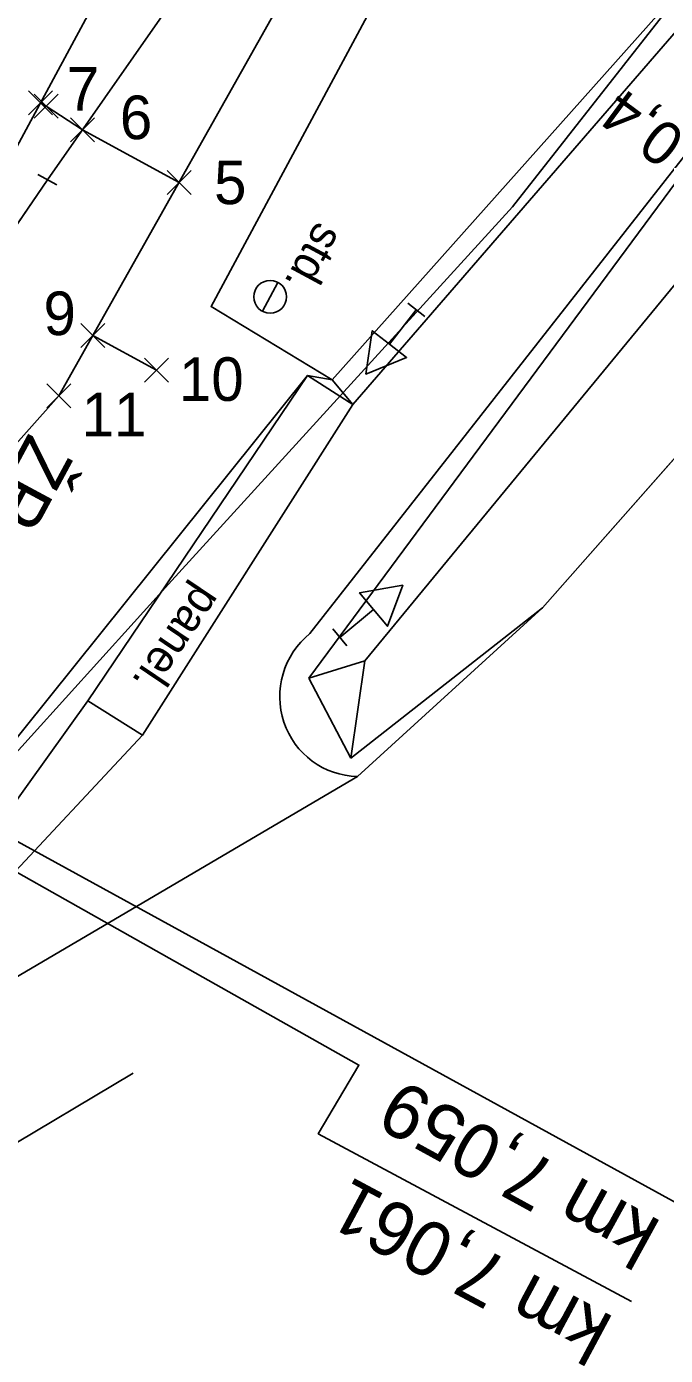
# Model space of a CAD drawing. Extents: x -795094 to -794639, y -1135368 to -1134681.
# Drawn here: x -794861.1 to -794831.7, y -1135032.7 to -1134971.7 of the extents above; entities that cross this region are included whole.
import ezdxf

# ---------------------------------------------------------------- set-up
doc = ezdxf.new("R2010")
doc.units = 0
for name, color, linetype in [('0381KM005-009P - Vrstva 1', 7, 'Continuous'), ('0381KM005-009P - Vrstva 16', 7, 'Continuous'), ('0381KM005-009P - Vrstva 17', 7, 'Continuous'), ('0381KM005-009P - Vrstva 2', 7, 'Continuous'), ('0381KM005-009P - Vrstva 3', 7, 'Continuous'), ('0381KM005-009P - Vrstva 41', 7, 'Continuous'), ('0381KM005-009P - Vrstva 48', 7, 'Continuous'), ('0381KM005-009P - Vrstva 49', 7, 'Continuous'), ('0381KM005-009P - Vrstva 51', 7, 'Continuous'), ('Default', 7, 'Continuous'), ('hran DP - hran DP', 7, 'Continuous'), ('PSR_C2_1_Lomove_body_Strunkovice - Vrstva 60', 7, 'Continuous'), ('PSR_C2_1_trasa_Strunkovice - Kabelová trasa', 7, 'Continuous'), ('vyt_sit - ohrožené', 7, 'Continuous')]:
    doc.layers.add(name, color=color, linetype=linetype)

msp = doc.modelspace()

# ---------------------------------------------------------------- linework, layer by layer
at = {"layer": '0381KM005-009P - Vrstva 1'}
for points in [[(-794788.584, -1134840.279), (-794803.188, -1134868.16), (-794810.376, -1134881.864), (-794818.661, -1134897.596), (-794826.62, -1134912.502), (-794834.335, -1134926.852), (-794861.916, -1134977.994)], [(-794786.958, -1134841.365), (-794793.838, -1134858.325), (-794800.908, -1134874.123), (-794807.726, -1134887.87), (-794826.516, -1134924.295), (-794833.336, -1134937.128), (-794839.366, -1134947.862), (-794840.749, -1134950.163), (-794846.082, -1134958.608), (-794850.879, -1134965.553), (-794860.098, -1134978.738)], [(-794860.098, -1134978.738), (-794870.638, -1134994.169), (-794874.381, -1135001.111), (-794874.769, -1135001.818)]]:
    msp.add_lwpolyline(points, dxfattribs=at)
at = {"layer": '0381KM005-009P - Vrstva 16'}
for p, q in [((-794848.162, -1134987.718), (-794858.241, -1135002.662)), ((-794846.073, -1134989.059), (-794848.162, -1134987.718)), ((-794848.162, -1134987.718), (-794847.031, -1134987.928)), ((-794847.031, -1134987.928), (-794846.073, -1134989.059)), ((-794858.241, -1135002.662), (-794855.733, -1135004.243))]:
    msp.add_line(p, q, dxfattribs=at)
at = {"layer": '0381KM005-009P - Vrstva 17'}
msp.add_lwpolyline([(-794829.977, -1134968.799), (-794847.031, -1134987.928), (-794852.583, -1134984.556), (-794841.01, -1134963.005)], dxfattribs=at)
at = {"layer": '0381KM005-009P - Vrstva 2'}
for p, q in [((-794859.658, -1134978.975), (-794860.538, -1134978.501)), ((-794860.098, -1134978.738), (-794870.638, -1134994.169)), ((-794830.917, -1135025.882), (-794874.769, -1135001.818))]:
    msp.add_line(p, q, dxfattribs=at)
at = {"layer": '0381KM005-009P - Vrstva 3'}
msp.add_lwpolyline([(-794875.274, -1135002.762), (-794845.796, -1135019.381), (-794847.666, -1135022.537), (-794833.282, -1135030.23)], dxfattribs=at)
at = {"layer": '0381KM005-009P - Vrstva 41'}
msp.add_line((-794849.515, -1134983.447), (-794850.229, -1134984.771), dxfattribs=at)
msp.add_circle((-794849.872, -1134984.109), 0.752, dxfattribs=at)
at = {"layer": '0381KM005-009P - Vrstva 49'}
for p, q in [((-794819.082, -1134962.417), (-794848.099, -1135001.612)), ((-794819.559, -1134969.298), (-794845.522, -1135000.83)), ((-794837.373, -1134998.386), (-794824.29, -1134983.577)), ((-794863.119, -1135006.371), (-794848.162, -1134987.718)), ((-794858.241, -1135002.662), (-794848.162, -1134987.718)), ((-794846.173, -1135005.288), (-794837.373, -1134998.386)), ((-794845.522, -1135000.83), (-794848.099, -1135001.612)), ((-794845.522, -1135000.83), (-794846.173, -1135005.288)), ((-794848.099, -1135001.612), (-794846.173, -1135005.288)), ((-794858.241, -1135002.662), (-794861.943, -1135007.826))]:
    msp.add_line(p, q, dxfattribs=at)
at = {"layer": '0381KM005-009P - Vrstva 51'}
for p, q in [((-794828.146, -1134968.345), (-794846.073, -1134989.059)), ((-794824.295, -1134969.269), (-794848.049, -1134999.571)), ((-794842.768, -1134985.014), (-794843.556, -1134984.398)), ((-794846.073, -1134989.059), (-794855.733, -1135004.243)), ((-794846.987, -1134999.359), (-794846.349, -1135000.129)), ((-794855.733, -1135004.243), (-794871.739, -1135021.338)), ((-794873.355, -1135030.02), (-794856.162, -1135019.751))]:
    msp.add_line(p, q, dxfattribs=at)
for points in [[(-794871.739, -1135021.338), (-794845.859, -1135006.134), (-794837.373, -1134998.386), (-794824.29, -1134983.577), (-794790.5, -1134931.648), (-794766.188, -1134894.559)], [(-794843.162, -1134984.706), (-794844.394, -1134986.281), (-794845.182, -1134985.665), (-794845.473, -1134987.66), (-794843.607, -1134986.897), (-794844.394, -1134986.281)], [(-794846.668, -1134999.744), (-794845.128, -1134998.468), (-794844.49, -1134999.238), (-794843.78, -1134997.351), (-794845.766, -1134997.698), (-794845.128, -1134998.468)]]:
    msp.add_lwpolyline(points, dxfattribs=at)
msp.add_ellipse((-794845.742, -1135002.436), major_axis=(-2.169, -3.012), ratio=0.990529, start_param=4.446216, end_param=6.879975, dxfattribs=at)
at = {"layer": 'hran DP - hran DP'}
for p, q in [((-794829.96, -1134968.76), (-794838.74, -1134979.98)), ((-794838.74, -1134979.98), (-794854.54, -1134997.31)), ((-794854.54, -1134997.31), (-794868.85, -1135013.13))]:
    msp.add_line(p, q, dxfattribs=at)
at = {"layer": 'PSR_C2_1_Lomove_body_Strunkovice - Vrstva 60'}
for p, q in [((-794860.962, -1134975.756), (-794859.862, -1134974.656)), ((-794859.862, -1134975.756), (-794860.962, -1134974.656)), ((-794860.702, -1134975.905), (-794859.602, -1134974.805)), ((-794859.602, -1134975.905), (-794860.702, -1134974.805)), ((-794859.042, -1134976.998), (-794857.942, -1134975.898)), ((-794857.942, -1134976.998), (-794859.042, -1134975.898)), ((-794854.604, -1134979.416), (-794853.504, -1134978.316)), ((-794853.504, -1134979.416), (-794854.604, -1134978.316)), ((-794858.556, -1134986.436), (-794857.456, -1134985.336)), ((-794857.456, -1134986.436), (-794858.556, -1134985.336)), ((-794855.633, -1134988.024), (-794854.533, -1134986.924)), ((-794854.533, -1134988.024), (-794855.633, -1134986.924)), ((-794860.117, -1134989.209), (-794859.017, -1134988.109)), ((-794859.017, -1134989.209), (-794860.117, -1134988.109))]:
    msp.add_line(p, q, dxfattribs=at)
at = {"layer": 'PSR_C2_1_trasa_Strunkovice - Kabelová trasa'}
for p, q in [((-794855.083, -1134987.474), (-794858.006, -1134985.886)), ((-794859.567, -1134988.659), (-794867.891, -1134997.98))]:
    msp.add_line(p, q, dxfattribs=at)
for points in [[(-794859.567, -1134988.659), (-794835.3, -1134945.549), (-794845.513, -1134940.368), (-794776.438, -1134812.998), (-794772.182, -1134815.082)], [(-794860.412, -1134975.206), (-794860.152, -1134975.355), (-794858.492, -1134976.448), (-794854.054, -1134978.866)]]:
    msp.add_lwpolyline(points, dxfattribs=at)

# ---------------------------------------------------------------- texts
at = {"layer": '0381KM005-009P - Vrstva 16'}
msp.add_text('panel.', height=1.5, rotation=236.00225, dxfattribs=at).set_placement((-794853.21, -1134997.208))
at = {"layer": '0381KM005-009P - Vrstva 2'}
msp.add_text('km 7,059', height=2.5, rotation=151.24157, dxfattribs=at).set_placement((-794831.826, -1135026.602))
at = {"layer": '0381KM005-009P - Vrstva 3'}
msp.add_text('km 7,061', height=2.5, rotation=151.86217, dxfattribs=at).set_placement((-794834.01, -1135030.99))
at = {"layer": '0381KM005-009P - Vrstva 41'}
msp.add_text('std.', height=1.5, rotation=241.66191, dxfattribs=at).set_placement((-794847.719, -1134980.594))
at = {"layer": '0381KM005-009P - Vrstva 48'}
msp.add_text('0,4', height=2, rotation=143.48656, dxfattribs=at).set_placement((-794830.703, -1134976.676))
at = {"layer": 'Default'}
for s, p in [('7', (-794859.208, -1134975.566)), ('6', (-794856.771, -1134976.871)), ('5', (-794852.446, -1134979.857)), ('9', (-794860.279, -1134985.869)), ('10', (-794854.06, -1134988.888)), ('11', (-794858.527, -1134990.512))]:
    msp.add_text(s, height=2, dxfattribs=at).set_placement(p)
at = {"layer": 'vyt_sit - ohrožené'}
msp.add_text('ŽP 3170', height=2.4, rotation=241.67136, dxfattribs=at).set_placement((-794860.936, -1134990.309))

doc.saveas('drawing.dxf')
